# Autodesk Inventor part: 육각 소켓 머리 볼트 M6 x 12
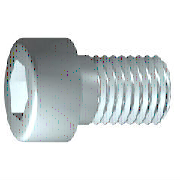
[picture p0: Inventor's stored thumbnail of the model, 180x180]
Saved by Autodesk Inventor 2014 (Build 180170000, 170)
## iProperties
IsCustomPart: 1
Created: 2012-02
Part Number: 육각 소켓 머리 볼트 M6 x 12
Material: 스테인리스강
Description: 6각 소켓 머리 캡 나사
Document SubType Name: Modeling
Standard: ISO 4762
Designer: mdu-01
Standard Revision: Fourth edition 2004-03-01
Standards Organization: ISO
Language: ko-KR
Size Designation: M6 x 12
Categories: <MemberInstance><Categories><Category DisplayName="조임쇠" InternalName="e4da775c-781d-43d5-af7c-5136215cf5a6" Mnemonic="FSTN"><Category DisplayName="볼트" InternalN
Density: 8.08 g/cm^3
Mass: 5.86427 g
Surface Area: 6.13705 cm^2
Volume: 0.725777 cm^3
Appearance: 반광택
Author: mdu-01
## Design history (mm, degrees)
sketch "스케치1"
  geometry: L1 (-1.333, 0)-(12, 0); L2 (12, 0)-(12, 3); L3 (12, 3)-(2.5, 3); L4 (2.5, 3)-(1.886, 3); L5 (1.886, 3)-(0, 3); L6 (0, 3)-(0, 5); L7 (0, 5)-(-6, 5); L8 (-6, 5)-(-6, 2.887); L9 (-6, 2.887)-(-3, 2.887); L10 (-3, 2.887)-(-1.333, 0); L11 (-9.6, 0)-(15.6, 0) reference; L12 (0, -1)-(0, 6) reference; L13 (2.5, 3)-(0, 3)
  constraints: 22 end point, 6 parallel, 2 collinear, 2 perpendicular, 1 horizontal, 1 point on line
  dimensions: "d1" = 9.5 distance from line of L3.end L2 (= GEL); "d2" = 0.61355 distance of L4.end L3.end (computed from GAL); "d3" = 6 distance between parallel lines of L8 L6 (= KOH); "d4" = 3 distance of L8.end L9.end (= INTI); "d5" = 60 deg angle of L10 L1; "d6" = 6 diameter of L3 L1 (= GD); "d7" = 6 diameter of L5 L1 (= BDM); "d8" = 5.7735 diameter of L9 L1 (= 1.1547 x SW); "d9" = 10 diameter of L7 L1 (= KOD); "d26" = 12 distance between parallel lines of L12 L2 (= NLG)
revolve "본체" sketch "스케치1" stored, may be unused: angle "d10" = 90 deg
sketch "스케치2"
  geometry: L1 (0, -7)-(0, 7) reference; L2 (-7, 0)-(7, 0) reference; L3 (2.887, 0)-(1.443, -2.5); L4 (1.443, -2.5)-(-1.443, -2.5); L5 (-1.443, -2.5)-(-2.887, 0); L6 (-2.887, 0)-(-1.443, 2.5); L7 (-1.443, 2.5)-(1.443, 2.5); L8 (1.443, 2.5)-(2.887, 0); 2 further points
  constraints: 12 end point, 1 coincident, 1 horizontal alignment, 1 point on line, 12 other
extrude "슬롯" join sketch "스케치2" stored distance "d11" = 10; taper "d12" = 0 deg
workplane "Work Plane1"
fillet "Fillet2" dims "d30" = 0.05 (= R)
body "Solid1"
fillet "모깎기1" dims "d17" = 0.6 (= RR)
feature "스레드" dims "d13" = 9.5 (= GEL), "d14" = 0
chamfer "모따기1" distance "d15" = 0.61345 (= -0.5 x SPD + 0.5 x GD); stored, may be unused: second distance "d16" = 0.61345 (= GUL), angle "d27" = 45 deg
other parameters: "GD" = 6 [user parameter; used in 2 equation terms], "NLG" = 12 [user parameter; used in 1 equation term], "GEL" = 9.5 [user parameter; used in 2 equation terms], "KOD" = 10 [user parameter; used in 1 equation term], "KOH" = 6 [user parameter; used in 1 equation term], "INTI" = 3 [user parameter; used in 1 equation term], "GAL" = 0.61345 (= 0.61345 x PTC) [user parameter; used in 1 equation term], "GUL" = 0.61345 (= 0.61345 x PTC) [user parameter; used in 1 equation term], "BDM" = 6 (= NND) [user parameter; used in 1 equation term], "SW" = 5 [user parameter; used in 2 equation terms], "RR" = 0.6 [user parameter; used in 1 equation term], "SPD" = 4.7731 (= NND - 1.2269 x PTC) [user parameter; used in 1 equation term], "d19" = 0, "d28" = 0, "d29" = 0, "R" = 0.05 [user parameter; used in 1 equation term], "TOA" = 30 deg [user parameter], "GD1" = 4.7731 (= THREADDIA - 1.2269 x PTC) [user parameter], "THREADDIA" = 6 [user parameter; used in 1 equation term], "FAWI" = 45 deg [user parameter], "PTC" = 1 [user parameter; used in 5 equation terms], "NND" = 6 [user parameter; used in 2 equation terms], "E0" = 5.775 (= 1.155 x SW) [user parameter]
